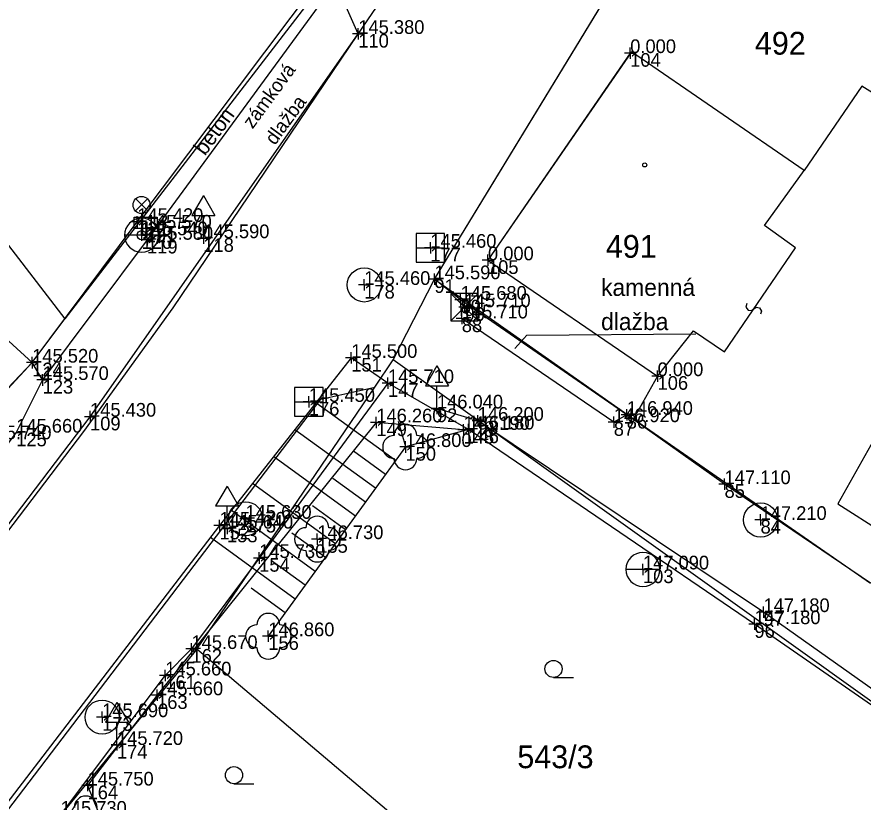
# Model space of a CAD drawing. Extents: x -748509 to -748117, y -967868 to -967533.
# Drawn here: x -748286.44 to -748249.31, y -967638.34 to -967603.91 of the extents above; entities that cross this region are included whole.
import ezdxf

# ---------------------------------------------------------------- set-up
doc = ezdxf.new("R2010")
doc.units = 0
for name, color, linetype in [('Body polohopisu', 7, 'Continuous'), ('Budovy', 7, 'Continuous'), ('Doplňkové značky', 7, 'Continuous'), ('Doplňující texty', 7, 'Continuous'), ('KM', 7, 'Continuous'), ('Ploty_opěrné zdi', 7, 'Continuous'), ('Popisy objektů_povrchů', 7, 'Continuous'), ('Rozhraní ploch', 7, 'Continuous'), ('Stromy_porost', 7, 'Continuous'), ('Vnitřní kresba', 7, 'Continuous'), ('Vstup na pozemek', 7, 'Continuous'), ('Výškopis', 7, 'Continuous'), ('Výšky bodů', 7, 'Continuous'), ('Značky IS', 7, 'Continuous'), ('Čísla bodů', 7, 'Continuous')]:
    doc.layers.add(name, color=color, linetype=linetype)

msp = doc.modelspace()

# ---------------------------------------------------------------- linework, layer by layer
at = {"layer": 'Body polohopisu'}
for p, q in [((-748271.46, -967604.65), (-748271.46, -967604.4)), ((-748271.46, -967604.65), (-748271.71, -967604.65)), ((-748271.46, -967604.65), (-748271.21, -967604.65)), ((-748271.46, -967604.65), (-748271.46, -967604.9)), ((-748259.53, -967605.49), (-748259.53, -967605.24)), ((-748259.53, -967605.49), (-748259.78, -967605.49)), ((-748259.53, -967605.49), (-748259.28, -967605.49)), ((-748259.53, -967605.49), (-748259.53, -967605.74)), ((-748281.16, -967612.9), (-748281.16, -967612.65)), ((-748281.16, -967612.9), (-748281.41, -967612.9)), ((-748281.16, -967612.9), (-748280.91, -967612.9)), ((-748281.16, -967612.9), (-748281.16, -967613.15)), ((-748280.79, -967613.19), (-748280.79, -967612.94)), ((-748280.79, -967613.19), (-748281.04, -967613.19)), ((-748280.97, -967613.48), (-748280.97, -967613.23)), ((-748280.79, -967613.19), (-748280.54, -967613.19)), ((-748280.79, -967613.19), (-748280.79, -967613.44)), ((-748280.73, -967613.68), (-748280.73, -967613.43)), ((-748278.26, -967613.61), (-748278.26, -967613.36)), ((-748280.97, -967613.48), (-748281.22, -967613.48)), ((-748280.73, -967613.68), (-748280.98, -967613.68)), ((-748280.97, -967613.48), (-748280.72, -967613.48)), ((-748280.97, -967613.48), (-748280.97, -967613.73)), ((-748280.73, -967613.68), (-748280.48, -967613.68)), ((-748280.73, -967613.68), (-748280.73, -967613.93)), ((-748278.26, -967613.61), (-748278.51, -967613.61)), ((-748278.26, -967613.61), (-748278.01, -967613.61)), ((-748278.26, -967613.61), (-748278.26, -967613.86)), ((-748268.3, -967614.03), (-748268.3, -967613.78)), ((-748268.3, -967614.03), (-748268.55, -967614.03)), ((-748268.3, -967614.03), (-748268.05, -967614.03)), ((-748268.3, -967614.03), (-748268.3, -967614.28)), ((-748265.77, -967614.58), (-748266.02, -967614.58)), ((-748265.77, -967614.58), (-748265.77, -967614.33)), ((-748265.77, -967614.58), (-748265.52, -967614.58)), ((-748265.77, -967614.58), (-748265.77, -967614.83)), ((-748268.12, -967615.41), (-748268.12, -967615.16)), ((-748271.2, -967615.66), (-748271.45, -967615.66)), ((-748271.2, -967615.66), (-748271.2, -967615.41)), ((-748271.2, -967615.66), (-748270.95, -967615.66)), ((-748271.2, -967615.66), (-748271.2, -967615.91)), ((-748268.12, -967615.41), (-748268.37, -967615.41)), ((-748268.12, -967615.41), (-748267.87, -967615.41)), ((-748268.12, -967615.41), (-748268.12, -967615.66)), ((-748266.97, -967616.31), (-748266.97, -967616.06)), ((-748266.97, -967616.31), (-748267.22, -967616.31)), ((-748266.97, -967616.31), (-748266.72, -967616.31)), ((-748266.97, -967616.31), (-748266.97, -967616.56)), ((-748266.8, -967616.64), (-748266.8, -967616.39)), ((-748266.8, -967616.64), (-748267.05, -967616.64)), ((-748266.8, -967616.64), (-748266.55, -967616.64)), ((-748266.8, -967616.64), (-748266.8, -967616.89)), ((-748266.92, -967617.13), (-748267.17, -967617.13)), ((-748266.92, -967617.13), (-748266.92, -967616.88)), ((-748266.92, -967617.13), (-748266.67, -967617.13)), ((-748266.92, -967617.13), (-748266.92, -967617.38)), ((-748271.77, -967618.86), (-748271.77, -967618.61)), ((-748285.77, -967619.07), (-748285.77, -967618.82)), ((-748271.77, -967618.86), (-748272.02, -967618.86)), ((-748271.77, -967618.86), (-748271.52, -967618.86)), ((-748271.77, -967618.86), (-748271.77, -967619.11)), ((-748285.77, -967619.07), (-748286.02, -967619.07)), ((-748285.77, -967619.07), (-748285.52, -967619.07)), ((-748285.77, -967619.07), (-748285.77, -967619.32)), ((-748285.31, -967619.83), (-748285.31, -967619.58)), ((-748270.16, -967619.97), (-748270.16, -967619.72)), ((-748258.33, -967619.66), (-748258.58, -967619.66)), ((-748258.33, -967619.66), (-748258.33, -967619.41)), ((-748258.33, -967619.66), (-748258.08, -967619.66)), ((-748258.33, -967619.66), (-748258.33, -967619.91)), ((-748285.31, -967619.83), (-748285.56, -967619.83)), ((-748285.31, -967619.83), (-748285.06, -967619.83)), ((-748285.31, -967619.83), (-748285.31, -967620.08)), ((-748270.16, -967619.97), (-748270.41, -967619.97)), ((-748270.16, -967619.97), (-748269.91, -967619.97)), ((-748270.16, -967619.97), (-748270.16, -967620.22)), ((-748273.63, -967620.79), (-748273.88, -967620.79)), ((-748273.63, -967620.79), (-748273.63, -967620.54)), ((-748273.63, -967620.79), (-748273.38, -967620.79)), ((-748273.63, -967620.79), (-748273.63, -967621.04)), ((-748268.01, -967621.08), (-748268.01, -967620.83)), ((-748283.23, -967621.44), (-748283.23, -967621.19)), ((-748268.01, -967621.08), (-748268.26, -967621.08)), ((-748268.01, -967621.08), (-748267.76, -967621.08)), ((-748268.01, -967621.08), (-748268.01, -967621.33)), ((-748259.68, -967621.36), (-748259.68, -967621.11)), ((-748283.23, -967621.44), (-748283.48, -967621.44)), ((-748283.23, -967621.44), (-748282.98, -967621.44)), ((-748283.23, -967621.44), (-748283.23, -967621.69)), ((-748270.67, -967621.69), (-748270.67, -967621.44)), ((-748266.22, -967621.62), (-748266.47, -967621.62)), ((-748266.22, -967621.62), (-748266.22, -967621.37)), ((-748266.22, -967621.62), (-748265.97, -967621.62)), ((-748266.22, -967621.62), (-748266.22, -967621.87)), ((-748260.25, -967621.68), (-748260.25, -967621.43)), ((-748259.68, -967621.36), (-748259.93, -967621.36)), ((-748259.68, -967621.36), (-748259.43, -967621.36)), ((-748259.68, -967621.36), (-748259.68, -967621.61)), ((-748270.67, -967621.69), (-748270.92, -967621.69)), ((-748270.67, -967621.69), (-748270.42, -967621.69)), ((-748270.67, -967621.69), (-748270.67, -967621.94)), ((-748266.63, -967622), (-748266.88, -967622)), ((-748266.84, -967622.02), (-748266.84, -967621.77)), ((-748266.63, -967622), (-748266.63, -967621.75)), ((-748266.63, -967622), (-748266.38, -967622)), ((-748266.63, -967622), (-748266.63, -967622.25)), ((-748260.25, -967621.68), (-748260.5, -967621.68)), ((-748260.25, -967621.68), (-748260, -967621.68)), ((-748260.25, -967621.68), (-748260.25, -967621.93)), ((-748286.47, -967622.14), (-748286.22, -967622.14)), ((-748266.84, -967622.02), (-748267.09, -967622.02)), ((-748266.84, -967622.02), (-748266.59, -967622.02)), ((-748266.84, -967622.02), (-748266.84, -967622.27)), ((-748269.39, -967622.77), (-748269.39, -967622.52)), ((-748269.39, -967622.77), (-748269.64, -967622.77)), ((-748269.39, -967622.77), (-748269.14, -967622.77)), ((-748269.39, -967622.77), (-748269.39, -967623.02)), ((-748255.39, -967624.4), (-748255.39, -967624.15)), ((-748255.39, -967624.4), (-748255.64, -967624.4)), ((-748255.39, -967624.4), (-748255.14, -967624.4)), ((-748255.39, -967624.4), (-748255.39, -967624.65)), ((-748276.41, -967625.92), (-748276.41, -967625.67)), ((-748277.55, -967626.22), (-748277.55, -967625.97)), ((-748276.41, -967625.92), (-748276.66, -967625.92)), ((-748276.41, -967625.92), (-748276.16, -967625.92)), ((-748276.41, -967625.92), (-748276.41, -967626.17)), ((-748253.81, -967625.97), (-748254.06, -967625.97)), ((-748253.81, -967625.97), (-748253.81, -967625.72)), ((-748253.81, -967625.97), (-748253.56, -967625.97)), ((-748253.81, -967625.97), (-748253.81, -967626.22)), ((-748277.55, -967626.22), (-748277.8, -967626.22)), ((-748277.55, -967626.22), (-748277.3, -967626.22)), ((-748277.55, -967626.22), (-748277.55, -967626.47)), ((-748277.22, -967626.35), (-748277.47, -967626.35)), ((-748277.22, -967626.35), (-748277.22, -967626.1)), ((-748277.22, -967626.35), (-748276.97, -967626.35)), ((-748277.22, -967626.35), (-748277.22, -967626.6)), ((-748273.26, -967626.81), (-748273.51, -967626.81)), ((-748273.26, -967626.81), (-748273.26, -967626.56)), ((-748273.26, -967626.81), (-748273.01, -967626.81)), ((-748273.26, -967626.81), (-748273.26, -967627.06)), ((-748275.81, -967627.64), (-748275.81, -967627.39)), ((-748275.81, -967627.64), (-748276.06, -967627.64)), ((-748275.81, -967627.64), (-748275.56, -967627.64)), ((-748275.81, -967627.64), (-748275.81, -967627.89)), ((-748258.97, -967628.14), (-748258.97, -967627.89)), ((-748258.97, -967628.14), (-748259.22, -967628.14)), ((-748258.97, -967628.14), (-748258.72, -967628.14)), ((-748258.97, -967628.14), (-748258.97, -967628.39)), ((-748253.68, -967630.01), (-748253.68, -967629.76)), ((-748253.68, -967630.01), (-748253.93, -967630.01)), ((-748253.68, -967630.01), (-748253.43, -967630.01)), ((-748253.68, -967630.01), (-748253.68, -967630.26)), ((-748254.08, -967630.54), (-748254.33, -967630.54)), ((-748254.08, -967630.54), (-748254.08, -967630.29)), ((-748254.08, -967630.54), (-748253.83, -967630.54)), ((-748254.08, -967630.54), (-748254.08, -967630.79)), ((-748275.41, -967631.07), (-748275.41, -967630.82)), ((-748275.41, -967631.07), (-748275.66, -967631.07)), ((-748275.41, -967631.07), (-748275.16, -967631.07)), ((-748275.41, -967631.07), (-748275.41, -967631.32)), ((-748278.78, -967631.63), (-748279.03, -967631.63)), ((-748278.78, -967631.63), (-748278.78, -967631.38)), ((-748278.78, -967631.63), (-748278.53, -967631.63)), ((-748278.78, -967631.63), (-748278.78, -967631.88)), ((-748279.93, -967632.79), (-748279.93, -967632.54)), ((-748279.93, -967632.79), (-748280.18, -967632.79)), ((-748279.93, -967632.79), (-748279.68, -967632.79)), ((-748279.93, -967632.79), (-748279.93, -967633.04)), ((-748280.29, -967633.66), (-748280.29, -967633.41)), ((-748280.29, -967633.66), (-748280.54, -967633.66)), ((-748280.29, -967633.66), (-748280.04, -967633.66)), ((-748280.29, -967633.66), (-748280.29, -967633.91)), ((-748282.7, -967634.62), (-748282.95, -967634.62)), ((-748282.7, -967634.62), (-748282.7, -967634.37)), ((-748282.7, -967634.62), (-748282.45, -967634.62)), ((-748282.7, -967634.62), (-748282.7, -967634.87)), ((-748282.05, -967635.84), (-748282.05, -967635.59)), ((-748282.05, -967635.84), (-748282.3, -967635.84)), ((-748282.05, -967635.84), (-748281.8, -967635.84)), ((-748282.05, -967635.84), (-748282.05, -967636.09)), ((-748283.34, -967637.62), (-748283.34, -967637.37)), ((-748283.34, -967637.62), (-748283.59, -967637.62)), ((-748283.34, -967637.62), (-748283.09, -967637.62)), ((-748283.34, -967637.62), (-748283.34, -967637.87))]:
    msp.add_line(p, q, dxfattribs=at)
at = {"layer": 'Budovy'}
for points in [[(-748259.53, -967605.49), (-748265.77, -967614.58), (-748258.33, -967619.66)], [(-748285.77, -967619.07), (-748293.53, -967627.23)]]:
    msp.add_lwpolyline(points, dxfattribs=at)
at = {"layer": 'Doplňkové značky'}
for p, q in [((-748281.234, -967612.418), (-748280.706, -967611.89)), ((-748280.698, -967612.415), (-748281.226, -967611.886)), ((-748278.26, -967611.744), (-748278.76, -967612.61)), ((-748278.26, -967611.744), (-748277.76, -967612.61)), ((-748280.97, -967612.53), (-748280.97, -967613.28)), ((-748278.76, -967612.61), (-748277.76, -967612.61)), ((-748278.26, -967613.61), (-748278.26, -967612.61)), ((-748278.51, -967613.61), (-748278.01, -967613.61)), ((-748268.01, -967619.214), (-748268.51, -967620.08)), ((-748268.01, -967619.214), (-748267.51, -967620.08)), ((-748268.51, -967620.08), (-748267.51, -967620.08)), ((-748268.01, -967621.08), (-748268.01, -967620.08)), ((-748268.26, -967621.08), (-748267.76, -967621.08)), ((-748277.22, -967624.484), (-748277.72, -967625.35)), ((-748277.22, -967624.484), (-748276.72, -967625.35)), ((-748277.72, -967625.35), (-748276.72, -967625.35)), ((-748277.22, -967626.35), (-748277.22, -967625.35)), ((-748277.47, -967626.35), (-748276.97, -967626.35)), ((-748282.05, -967633.974), (-748282.55, -967634.84)), ((-748282.05, -967633.974), (-748281.55, -967634.84)), ((-748282.55, -967634.84), (-748281.55, -967634.84)), ((-748282.05, -967635.84), (-748282.05, -967634.84)), ((-748282.3, -967635.84), (-748281.8, -967635.84))]:
    msp.add_line(p, q, dxfattribs=at)
for centre, radius in [((-748280.97, -967612.155), 0.375), ((-748280.97, -967613.48), 0.2)]:
    msp.add_circle(centre, radius, dxfattribs=at)
at = {"layer": 'Doplňující texty'}
msp.add_lwpolyline([(-748264.599, -967618.446), (-748264.06, -967617.87), (-748256.652, -967617.808)], dxfattribs=at)
at = {"layer": 'KM'}
for p, q in [((-748303.27, -967592.59), (-748284.33, -967617.15)), ((-748268.12, -967615.41), (-748255.88, -967595.31)), ((-748270.17, -967598.74), (-748284.33, -967617.15)), ((-748285.77, -967619.07), (-748303.96, -967602.45)), ((-748269.93, -967618.95), (-748268.12, -967615.41)), ((-748268.12, -967615.41), (-748259.38, -967621.54)), ((-748285.77, -967619.07), (-748284.33, -967617.15)), ((-748270.74, -967620.14), (-748269.93, -967618.95)), ((-748278.55, -967631.64), (-748270.74, -967620.14)), ((-748259.38, -967621.54), (-748248.98, -967628.74)), ((-748278.55, -967631.64), (-748284.52, -967638.9)), ((-748262.897, -967632.88), (-748262.022, -967632.88)), ((-748276.917, -967637.54), (-748276.042, -967637.54))]:
    msp.add_line(p, q, dxfattribs=at)
for points in [[(-748245.234, -967554.317), (-748248, -967560.09), (-748251.25, -967566.35), (-748259.98, -967584.86), (-748268.35, -967600.05), (-748271.49, -967604.68), (-748279.6, -967616.66), (-748283.52, -967622.09), (-748309.26, -967655.94), (-748313.11, -967660.69), (-748315.81, -967663.73), (-748339.38, -967691.21), (-748366.68, -967719.8), (-748398.22, -967751.73), (-748421.72, -967775.27), (-748446.6, -967799.82), (-748468.93, -967821.53), (-748491.86, -967845.1), (-748500.525, -967854.438)], [(-748239.53, -967613.07), (-748245.95, -967609.07), (-748249.36, -967606.94), (-748251.89, -967610.64), (-748259.47, -967605.44), (-748265.77, -967614.58), (-748258.33, -967619.66), (-748259.38, -967621.54)], [(-748231.71, -967646.39), (-748235.78, -967643.43), (-748239.43, -967640.68), (-748244.42, -967637.16), (-748269.93, -967618.95)], [(-748326.81, -967667.85), (-748323.4, -967663.68), (-748322.52, -967662.81), (-748320.84, -967661.016), (-748318.15, -967663.66), (-748309.61, -967654.82), (-748307.98, -967651.29), (-748308.35, -967650.91), (-748310.6, -967648.68), (-748293.45, -967627.35), (-748285.77, -967619.07)], [(-748313.39, -967675.71), (-748297.69, -967654.72), (-748296.75, -967652.08), (-748293.15, -967646.97), (-748273.11, -967620.67), (-748270.74, -967620.14)], [(-748261.53, -967645.48), (-748269.74, -967639.09), (-748278.55, -967631.64)]]:
    msp.add_lwpolyline(points, dxfattribs=at)
for centre, radius in [((-748258.893, -967610.4), 0.0875), ((-748262.896, -967632.505), 0.375), ((-748276.916, -967637.165), 0.375)]:
    msp.add_circle(centre, radius, dxfattribs=at)
at = {"layer": 'Ploty_opěrné zdi'}
for points in [[(-748259.68, -967621.36), (-748266.97, -967616.31), (-748268.12, -967615.41), (-748255.88, -967595.31)], [(-748285.77, -967619.07), (-748281.16, -967612.9), (-748273.3, -967602.43)], [(-748266.63, -967622), (-748270.16, -967619.97), (-748275.81, -967627.64), (-748278.78, -967631.63)], [(-748239.43, -967640.68), (-748254.08, -967630.54), (-748266.63, -967622)], [(-748248.98, -967628.74), (-748255.39, -967624.4)], [(-748280.29, -967633.66), (-748283.34, -967637.62), (-748282.22, -967640.4)]]:
    msp.add_lwpolyline(points, dxfattribs=at)
at = {"layer": 'Rozhraní ploch'}
for points in [[(-748318.15, -967663.66), (-748318.74, -967664.07), (-748320.08, -967663.63), (-748320.81, -967664.8), (-748317.31, -967664.84), (-748311.17, -967658.18), (-748308.97, -967655.34), (-748295.87, -967638.09), (-748283.23, -967621.44), (-748271.46, -967604.65), (-748272.46, -967602.39)], [(-748272.46, -967602.39), (-748280.73, -967613.68), (-748285.31, -967619.83), (-748286.47, -967622.14), (-748292.61, -967630.26), (-748297.64, -967636.89), (-748299.99, -967634.86)], [(-748259.68, -967621.36), (-748260.25, -967621.68), (-748266.92, -967617.13), (-748266.97, -967616.31)], [(-748270.16, -967619.97), (-748271.77, -967618.86), (-748277.55, -967626.22), (-748293.79, -967647.39), (-748292.07, -967648.57)], [(-748285.31, -967619.83), (-748285.77, -967619.07)], [(-748199.23, -967672.68), (-748197.54, -967670.59), (-748208.01, -967662.84), (-748218.68, -967655.21), (-748230, -967646.93), (-748239.49, -967640.06), (-748253.68, -967630.01), (-748266.22, -967621.62), (-748268.01, -967621.08)], [(-748281.29, -967641.63), (-748284.52, -967638.9), (-748279.93, -967632.79), (-748278.78, -967631.63)]]:
    msp.add_lwpolyline(points, dxfattribs=at)
at = {"layer": 'Stromy_porost'}
msp.add_lwpolyline([(-748266.84, -967622.02), (-748270.67, -967621.69), (-748280.29, -967633.66)], dxfattribs=at)
for centre in [(-748269.39, -967622.77), (-748273.26, -967626.81), (-748275.41, -967631.07)]:
    msp.add_circle(centre, 0.0005, dxfattribs=at)
for centre, start, end in [((-748269.39, -967622.27), 0, 180), ((-748269.89, -967622.77), 90, 270), ((-748268.89, -967622.77), 270, 90), ((-748269.39, -967623.27), 180, 360), ((-748273.26, -967626.31), 0, 180), ((-748273.76, -967626.81), 90, 270), ((-748272.76, -967626.81), 270, 90), ((-748273.26, -967627.31), 180, 360), ((-748275.41, -967630.57), 0, 180), ((-748275.91, -967631.07), 90, 270), ((-748274.91, -967631.07), 270, 90), ((-748275.41, -967631.57), 180, 360), ((-748283.42, -967638.58), 0, 180)]:
    msp.add_arc(centre, 0.5, start, end, dxfattribs=at)
at = {"layer": 'Vnitřní kresba'}
for p, q in [((-748253.64, -967613.06), (-748251.89, -967610.64)), ((-748252.28, -967614.03), (-748253.64, -967613.06)), ((-748255.4, -967618.6), (-748252.28, -967614.03)), ((-748258.33, -967619.66), (-748256.76, -967617.68)), ((-748256.76, -967617.68), (-748255.4, -967618.6)), ((-748246.83, -967618.87), (-748250.42, -967625.26)), ((-748250.42, -967625.26), (-748247.66, -967627.02))]:
    msp.add_line(p, q, dxfattribs=at)
msp.add_lwpolyline([(-748254.408, -967616.481), (-748254.451, -967616.633), (-748254.357, -967616.77), (-748254.206, -967616.788), (-748254, -967616.638), (-748253.851, -967616.667), (-748253.77, -967616.807), (-748253.816, -967616.945)], dxfattribs=at)
at = {"layer": 'Vstup na pozemek'}
msp.add_lwpolyline([(-748255.39, -967624.4), (-748259.68, -967621.36)], dxfattribs=at)
at = {"layer": 'Výškopis'}
for points in [[(-748269.824, -967623.369), (-748273.32, -967620.833)], [(-748266.63, -967622), (-748269.39, -967622.77), (-748275.41, -967631.07)], [(-748269.38, -967622.767), (-748269.692, -967621.648)], [(-748270.705, -967624.583), (-748274.247, -967622.014)], [(-748270.265, -967623.976), (-748271.672, -967622.955)], [(-748271.586, -967625.797), (-748275.174, -967623.195)], [(-748271.145, -967625.19), (-748272.571, -967624.156)], [(-748272.466, -967627.011), (-748276.101, -967624.375)], [(-748273.347, -967628.226), (-748277.028, -967625.556)], [(-748272.026, -967626.404), (-748273.471, -967625.357)], [(-748274.228, -967629.44), (-748277.949, -967626.741)], [(-748272.907, -967627.619), (-748274.37, -967626.557)], [(-748273.787, -967628.833), (-748275.269, -967627.758)], [(-748274.668, -967630.047), (-748276.163, -967628.963)]]:
    msp.add_lwpolyline(points, dxfattribs=at)
at = {"layer": 'Značky IS'}
for p, q in [((-748280.223, -967613.48), (-748281.718, -967613.48)), ((-748268.926, -967614.03), (-748267.676, -967614.03)), ((-748267.4, -967616.04), (-748266.2, -967617.24)), ((-748266.2, -967616.04), (-748267.4, -967617.24)), ((-748274.255, -967620.79), (-748273.005, -967620.79)), ((-748258.223, -967628.14), (-748259.718, -967628.14))]:
    msp.add_line(p, q, dxfattribs=at)
for points in [[(-748281.29, -967613.19), (-748281.29, -967612.69), (-748280.29, -967612.69), (-748280.29, -967613.19)], [(-748268.926, -967614.657), (-748267.674, -967614.657), (-748267.674, -967613.403), (-748268.926, -967613.403)], [(-748267.4, -967617.24), (-748266.2, -967617.24), (-748266.2, -967616.04), (-748267.4, -967616.04)], [(-748274.255, -967621.417), (-748273.004, -967621.417), (-748273.004, -967620.163), (-748274.255, -967620.163)]]:
    msp.add_lwpolyline(points, close=True, dxfattribs=at)
for centre in [(-748271.2, -967615.66), (-748276.41, -967625.92), (-748253.81, -967625.97), (-748282.7, -967634.62)]:
    msp.add_circle(centre, 0.75, dxfattribs=at)
for centre, start, end in [((-748280.97, -967613.48), 0, 180), ((-748280.97, -967613.48), 180, 0), ((-748258.97, -967628.14), 0, 180), ((-748258.97, -967628.14), 180, 0)]:
    msp.add_arc(centre, 0.747, start, end, dxfattribs=at)

# ---------------------------------------------------------------- texts
at = {"layer": 'KM'}
for s, p in [('492', (-748254.06, -967605.56)), ('491', (-748260.6, -967614.47)), ('543/3', (-748264.483, -967636.86))]:
    msp.add_text(s, height=1, dxfattribs=at).set_placement(p)
at = {"layer": 'Popisy objektů_povrchů'}
for s, height, p in [('zámková', 0.6075, (-748276.1, -967608.848)), ('dlažba', 0.6075, (-748275.12, -967609.566)), ('beton', 0.675, (-748278.189, -967610.026))]:
    msp.add_text(s, height=height, rotation=53.777, dxfattribs=at).set_placement(p)
for s, p in [('kamenná', (-748260.809, -967616.143)), ('dlažba', (-748260.809, -967617.643))]:
    msp.add_text(s, height=0.75, dxfattribs=at).set_placement(p)
at = {"layer": 'Výšky bodů'}
for s, p in [('145.380', (-748271.46, -967604.65)), ('0.000', (-748259.53, -967605.49)), ('145.420', (-748281.16, -967612.9)), ('145.570', (-748280.79, -967613.19)), ('145.540', (-748280.97, -967613.48)), ('145.580', (-748280.73, -967613.68)), ('145.590', (-748278.26, -967613.61)), ('145.460', (-748268.3, -967614.03)), ('0.000', (-748265.77, -967614.58)), ('145.590', (-748268.12, -967615.41)), ('145.460', (-748271.2, -967615.66)), ('145.680', (-748266.97, -967616.31)), ('145.710', (-748266.8, -967616.64)), ('145.710', (-748266.92, -967617.13)), ('145.500', (-748271.77, -967618.86)), ('145.520', (-748285.77, -967619.07)), ('145.570', (-748285.31, -967619.83)), ('145.710', (-748270.16, -967619.97)), ('0.000', (-748258.33, -967619.66)), ('145.450', (-748273.63, -967620.79)), ('146.040', (-748268.01, -967621.08)), ('145.430', (-748283.23, -967621.44)), ('146.940', (-748259.68, -967621.36)), ('146.260', (-748270.67, -967621.69)), ('146.200', (-748266.22, -967621.62)), ('146.920', (-748260.25, -967621.68)), ('145.660', (-748286.47, -967622.14)), ('146.190', (-748266.84, -967622.02)), ('146.180', (-748266.63, -967622)), ('145.740', (-748287.82, -967622.43)), ('146.800', (-748269.39, -967622.77)), ('147.110', (-748255.39, -967624.4)), ('145.630', (-748276.41, -967625.92)), ('145.470', (-748277.55, -967626.22)), ('147.210', (-748253.81, -967625.97)), ('145.640', (-748277.22, -967626.35)), ('146.730', (-748273.26, -967626.81)), ('145.730', (-748275.81, -967627.64)), ('147.090', (-748258.97, -967628.14)), ('147.180', (-748253.68, -967630.01)), ('147.180', (-748254.08, -967630.54)), ('146.860', (-748275.41, -967631.07)), ('145.670', (-748278.78, -967631.63)), ('145.660', (-748279.93, -967632.79)), ('145.660', (-748280.29, -967633.66)), ('145.690', (-748282.7, -967634.62)), ('145.720', (-748282.05, -967635.84)), ('145.750', (-748283.34, -967637.62)), ('145.730', (-748284.52, -967638.9))]:
    msp.add_text(s, height=0.6, dxfattribs=at).set_placement(p)
at = {"layer": 'Čísla bodů'}
for s, p in [('110', (-748271.46, -967605.25)), ('104', (-748259.53, -967606.09)), ('122', (-748281.16, -967613.5)), ('121', (-748280.79, -967613.79)), ('120', (-748280.97, -967614.08)), ('119', (-748280.73, -967614.28)), ('118', (-748278.26, -967614.21)), ('177', (-748268.3, -967614.63)), ('105', (-748265.77, -967615.18)), ('178', (-748271.2, -967616.26)), ('91', (-748268.12, -967616.01)), ('89', (-748266.97, -967616.91)), ('90', (-748266.8, -967617.24)), ('88', (-748266.92, -967617.73)), ('151', (-748271.77, -967619.46)), ('124', (-748285.77, -967619.67)), ('106', (-748258.33, -967620.26)), ('123', (-748285.31, -967620.43)), ('147', (-748270.16, -967620.57)), ('176', (-748273.63, -967621.39)), ('92', (-748268.01, -967621.68)), ('109', (-748283.23, -967622.04)), ('93', (-748266.22, -967622.22)), ('86', (-748259.68, -967621.96)), ('149', (-748270.67, -967622.29)), ('146', (-748266.63, -967622.6)), ('87', (-748260.25, -967622.28)), ('125', (-748286.47, -967622.74)), ('148', (-748266.84, -967622.62)), ('150', (-748269.39, -967623.37)), ('85', (-748255.39, -967625)), ('175', (-748276.41, -967626.52)), ('84', (-748253.81, -967626.57)), ('152', (-748277.55, -967626.82)), ('153', (-748277.22, -967626.95)), ('155', (-748273.26, -967627.41)), ('154', (-748275.81, -967628.24)), ('103', (-748258.97, -967628.74)), ('97', (-748253.68, -967630.61)), ('96', (-748254.08, -967631.14)), ('156', (-748275.41, -967631.67)), ('162', (-748278.78, -967632.23)), ('161', (-748279.93, -967633.39)), ('163', (-748280.29, -967634.26)), ('173', (-748282.7, -967635.22)), ('174', (-748282.05, -967636.44)), ('164', (-748283.34, -967638.22))]:
    msp.add_text(s, height=0.6, dxfattribs=at).set_placement(p)

doc.saveas('drawing.dxf')
